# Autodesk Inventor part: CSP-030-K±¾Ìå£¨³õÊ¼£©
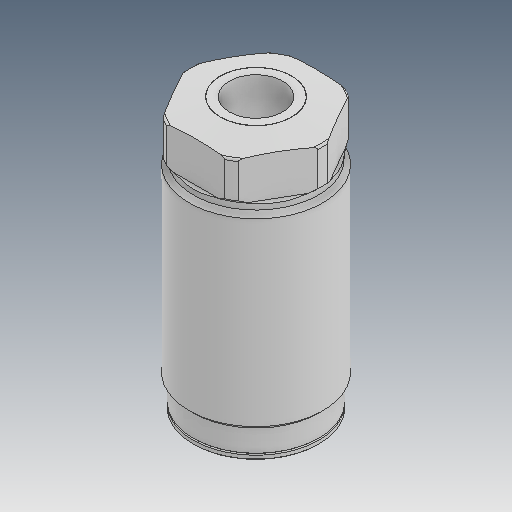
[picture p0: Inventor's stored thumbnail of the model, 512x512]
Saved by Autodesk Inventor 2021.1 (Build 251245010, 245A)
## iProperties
Created: 2019-01
Part Number: CSP-030-K±¾Ìå£¨³õÊ¼£©
Material: Ogólny
Document SubType Name: Modeling
Designer: user
Density: 1 g/cm^3
Appearance: Domyślna
Author: user
Revision Number: ÈÎºÎ
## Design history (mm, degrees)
feature "Ô²½Ç2"
node "Bryła1"
